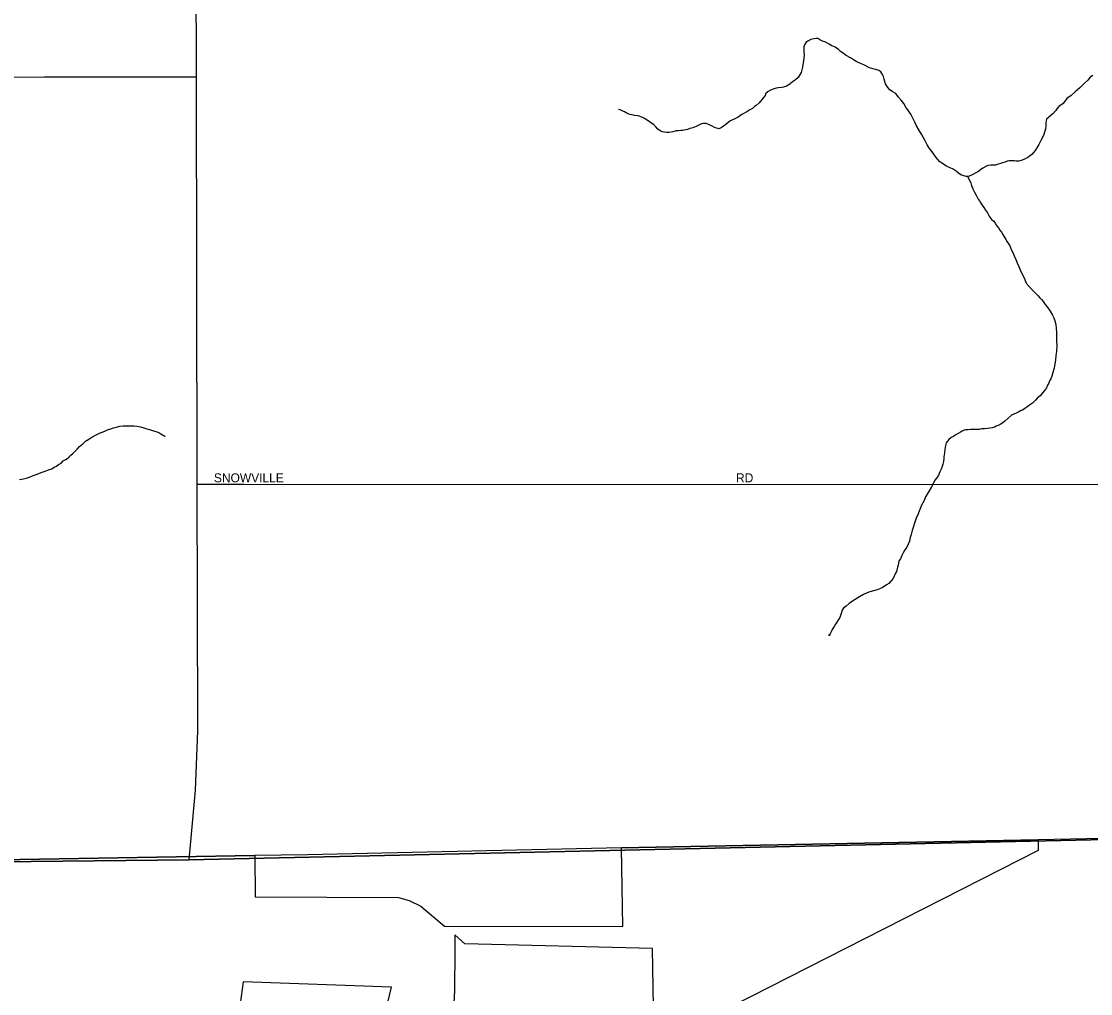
# Model space of a CAD drawing. Extents: x 2010165 to 2382125, y 1060529 to 1407316.
# Drawn here: x 2207531 to 2213496, y 1194340 to 1199766 of the extents above; entities that cross this region are included whole.
import ezdxf

# ---------------------------------------------------------------- set-up
doc = ezdxf.new("R2010")
doc.units = 0
for name, color, linetype in [('GM_X_Adjacent_County', 7, 'Continuous'), ('GM_X_City_Street', 7, 'Continuous'), ('GM_X_City_Street_Text', 7, 'Continuous'), ('GM_X_Corporation', 7, 'Continuous'), ('GM_X_County', 7, 'Continuous'), ('GM_X_Minor_River', 7, 'Continuous'), ('GM_X_State_Route', 7, 'Continuous')]:
    doc.layers.add(name, color=color, linetype=linetype)

msp = doc.modelspace()

# ---------------------------------------------------------------- linework, layer by layer
at = {"layer": 'GM_X_Adjacent_County'}
msp.add_lwpolyline([(2192737.6, 1194839.7), (2198605.6, 1194974.2), (2199009.7, 1194982.8), (2204631.8, 1195039.6), (2205347.9, 1195050.5), (2205386.6, 1195051.1), (2205910.4, 1195059.1), (2205996.9, 1195060.4), (2208466.7, 1195086.6), (2214754.4, 1195227), (2218436, 1195308), (2224284, 1195428.9)], dxfattribs=at)
at = {"layer": 'GM_X_City_Street'}
for points in [[(2204724.3, 1199441.2), (2204863.3, 1199441.5), (2205439.3, 1199448.7), (2205835.5, 1199453.6), (2206070.1, 1199453.8), (2207659.8, 1199455.3)], [(2207659.8, 1199455.3), (2208507.6, 1199456)], [(2208511.1, 1197183.4), (2208774.3, 1197183.4)], [(2208774.3, 1197183.4), (2214667.7, 1197181.8), (2216899.7, 1197183.8), (2217311.7, 1197172.5), (2217783.8, 1197165.3), (2218121.8, 1197163.9), (2218293.8, 1197148.2), (2218441.8, 1197144.5), (2218681.8, 1197136.8), (2218819.8, 1197131.1), (2219725.7, 1197182.9)]]:
    msp.add_lwpolyline(points, dxfattribs=at)
at = {"layer": 'GM_X_Corporation'}
for points in [[(2225489.9, 1195453.9), (2213202.5, 1195199), (2210879.2, 1195154.6), (2209126.8, 1195115.5), (2208833.2, 1195110.6), (2205335.3, 1195051.8), (2197309.3, 1194916.9), (2196632.3, 1194905.5), (2196205.1, 1208275.6), (2197215.9, 1208288.2), (2199497, 1208304.3), (2199654.4, 1208314.4), (2199834.9, 1208326), (2199872.3, 1208332.6), (2204445.3, 1208317.3), (2204662.3, 1210529.8), (2204447.2, 1221938.7)], [(2205380.8, 1189374), (2205335.3, 1195051.8), (2208833.2, 1195110.6), (2208834.3, 1194880.4), (2209634.8, 1194876.7), (2209694, 1194860.1), (2209758.7, 1194828.6), (2209892.1, 1194715.8), (2210886.7, 1194715.4), (2210879.2, 1195154.6), (2213202.5, 1195199), (2213203.5, 1195138.9), (2211060.9, 1194048.1), (2211051.6, 1194591.3), (2210004.4, 1194618.8), (2209949.2, 1194667.7), (2209948.6, 1194580.7), (2209946.9, 1194358.4), (2209934.6, 1194108.7)], [(2209535.9, 1194128.5), (2209596.2, 1194375.8), (2208768, 1194406.3), (2208752.2, 1194282.5)]]:
    msp.add_lwpolyline(points, dxfattribs=at)
at = {"layer": 'GM_X_County'}
msp.add_lwpolyline([(2224284, 1195428.9), (2218436, 1195308), (2214754.4, 1195227), (2208466.7, 1195086.6), (2205996.9, 1195060.4), (2205910.4, 1195059.1), (2205386.6, 1195051.1), (2205347.9, 1195050.5), (2204631.8, 1195039.6), (2199009.7, 1194982.8), (2198605.6, 1194974.2), (2192737.6, 1194839.7)], dxfattribs=at)
at = {"layer": 'GM_X_Minor_River'}
for points in [[(2212925, 1198961.5), (2212911, 1198955.3), (2212895.1, 1198947), (2212881.2, 1198936.8), (2212867.3, 1198926.6), (2212827.5, 1198906), (2212813.6, 1198899.8), (2212801.5, 1198899.7), (2212783.4, 1198905.4), (2212771.4, 1198909.3), (2212759.2, 1198919.2), (2212745.1, 1198929.1), (2212728.9, 1198940.9), (2212712.7, 1198948.7), (2212694.6, 1198956.5), (2212680.5, 1198964.4), (2212666.3, 1198974.2), (2212654.2, 1198982.1), (2212644, 1198994), (2212633.9, 1199005.9), (2212621.6, 1199023.9), (2212611.4, 1199037.8), (2212597.1, 1199055.7), (2212584.8, 1199077.6), (2212570.5, 1199103.5), (2212552, 1199135.4), (2212537.7, 1199161.3), (2212525.4, 1199183.3), (2212515.1, 1199203.2), (2212504.8, 1199225.2), (2212492.5, 1199247.1), (2212480.2, 1199267), (2212465.9, 1199286.9), (2212453.6, 1199306.9), (2212439.3, 1199326.8), (2212423.1, 1199344.6), (2212408.8, 1199362.5), (2212388.6, 1199374.3), (2212376.5, 1199384.2), (2212366.3, 1199394.1), (2212358.1, 1199408), (2212352, 1199418), (2212347.8, 1199430), (2212343.6, 1199444), (2212341.4, 1199458), (2212335.3, 1199470), (2212325.1, 1199483.9), (2212315, 1199491.8), (2212302.9, 1199495.7), (2212288.8, 1199499.5), (2212274.7, 1199503.4), (2212262.7, 1199507.2), (2212230.4, 1199522.9), (2212212.3, 1199530.7), (2212192.1, 1199540.5), (2212174, 1199550.3), (2212155.8, 1199562.1), (2212131.5, 1199575.8), (2212115.4, 1199587.7), (2212101.2, 1199597.5), (2212089, 1199609.4), (2212070.8, 1199621.2), (2212052.7, 1199629), (2212036.5, 1199638.9), (2212024.4, 1199646.8), (2212012.4, 1199650.6), (2212000.3, 1199654.5), (2211986.2, 1199662.3), (2211974, 1199670.2), (2211964, 1199670.1), (2211952, 1199667.9), (2211936, 1199663.7), (2211918.1, 1199655.4), (2211908.2, 1199649.3), (2211900.3, 1199635.1), (2211896.5, 1199623), (2211896.7, 1199609), (2211896.8, 1199596.9), (2211897.1, 1199574.8), (2211893.5, 1199546.7), (2211887.9, 1199510.5), (2211880.3, 1199480.3), (2211870.5, 1199462.1), (2211864.7, 1199451.9), (2211848.8, 1199439.7), (2211832.9, 1199427.4), (2211817.1, 1199415.2), (2211799.2, 1199404.9), (2211783.2, 1199398.7), (2211773.2, 1199396.6), (2211755.2, 1199394.3), (2211741.2, 1199392.1), (2211725.2, 1199387.9), (2211709.3, 1199381.7), (2211697.4, 1199373.5), (2211681.5, 1199361.3), (2211679.6, 1199351.2), (2211663.9, 1199330.9), (2211646.1, 1199310.6), (2211630.3, 1199296.3), (2211620.3, 1199290.2)], [(2213507.5, 1199462.9), (2213493.6, 1199454.7), (2213479.8, 1199438.4), (2213460, 1199418.1), (2213436.2, 1199395.7), (2213410.5, 1199373.3), (2213386.7, 1199352.9), (2213362.9, 1199334.5), (2213343.2, 1199308.2), (2213319.4, 1199289.8), (2213307.5, 1199277.6), (2213301.7, 1199267.5), (2213287.9, 1199251.2), (2213250.2, 1199220.6), (2213246.5, 1199198.5), (2213246.7, 1199180.4), (2213244.9, 1199166.3), (2213241.1, 1199152.2), (2213233.4, 1199128.1), (2213219.6, 1199103.8), (2213207.9, 1199079.5), (2213196.2, 1199059.3), (2213186.4, 1199045.1), (2213168.6, 1199022.8), (2213144.8, 1199006.4), (2213122.9, 1198994.1), (2213108.9, 1198989.9), (2213095, 1198985.7), (2213078.9, 1198985.5), (2213068.9, 1198987.4), (2213050.9, 1198987.2), (2213040.8, 1198987.1), (2213030.8, 1198984.9), (2213016.9, 1198980.7), (2213004.9, 1198976.6), (2212992.9, 1198972.4), (2212981, 1198968.2), (2212965, 1198964), (2212951, 1198963.8), (2212939, 1198963.7), (2212925, 1198961.5)], [(2211620.3, 1199290.2), (2211610.4, 1199280), (2211594.5, 1199271.8), (2211578.6, 1199261.6), (2211550.8, 1199245.1), (2211528.9, 1199230.8), (2211507, 1199220.5), (2211495.1, 1199214.3), (2211483.1, 1199208.1), (2211461.3, 1199189.8), (2211447.4, 1199181.6), (2211435.5, 1199171.4), (2211421.6, 1199165.2), (2211397.4, 1199172.9), (2211385.3, 1199180.8), (2211373.2, 1199186.6), (2211361.1, 1199192.5), (2211351.1, 1199196.4), (2211337, 1199196.2), (2211325, 1199194.1), (2211313.1, 1199187.9), (2211299.1, 1199181.7), (2211277.2, 1199171.4), (2211259.3, 1199167.1), (2211247.3, 1199162.9), (2211235.3, 1199160.8), (2211221.3, 1199156.6), (2211209.3, 1199156.4), (2211197.3, 1199154.3), (2211183.3, 1199154.1), (2211165.3, 1199149.9), (2211143.3, 1199145.6), (2211129.3, 1199145.4), (2211119.3, 1199147.3), (2211105.2, 1199149.1), (2211095.1, 1199155), (2211081, 1199164.8), (2211070.8, 1199176.8), (2211058.6, 1199188.7), (2211022.2, 1199214.3), (2211008.1, 1199224.2), (2210991.9, 1199232), (2210971.8, 1199237.8), (2210951.8, 1199239.5), (2210937.7, 1199243.3), (2210925.6, 1199245.2), (2210915.6, 1199249.1), (2210905.5, 1199255), (2210895.4, 1199260.9), (2210883.3, 1199266.7), (2210871.2, 1199272.6), (2210861.2, 1199274.5)], [(2212808.2, 1198899.7), (2212828.1, 1198863.8), (2212832.2, 1198849.8), (2212838.5, 1198831.9), (2212848.8, 1198811.9), (2212857, 1198795.9), (2212863.2, 1198784), (2212869.3, 1198774), (2212875.4, 1198764.1), (2212883.6, 1198752.1), (2212891.8, 1198740.2), (2212900, 1198726.2), (2212910.2, 1198712.3), (2212920.4, 1198696.4), (2212930.7, 1198678.4), (2212942.9, 1198660.5), (2212955.1, 1198650.6), (2212963.2, 1198638.7), (2212971.4, 1198626.7), (2212981.6, 1198612.8), (2212989.8, 1198600.9), (2212997.9, 1198588.9), (2213006.1, 1198577), (2213012.2, 1198567), (2213022.5, 1198549.1), (2213030.7, 1198535.1), (2213043, 1198517.2), (2213049.1, 1198503.2), (2213055.3, 1198489.2), (2213061.5, 1198475.3), (2213069.8, 1198457.3), (2213078.1, 1198437.3), (2213086.3, 1198417.4), (2213094.6, 1198397.4), (2213107, 1198369.4), (2213119.3, 1198345.5), (2213129.6, 1198325.5), (2213135.9, 1198305.6), (2213168.4, 1198269.8), (2213180.6, 1198255.9), (2213192.7, 1198246), (2213202.9, 1198234.1), (2213211.1, 1198224.2), (2213221.2, 1198214.3), (2213231.4, 1198202.3), (2213241.6, 1198186.4), (2213253.8, 1198172.5), (2213270.2, 1198148.6), (2213282.5, 1198126.7), (2213290.7, 1198110.7), (2213296.9, 1198094.8), (2213301.2, 1198074.7), (2213303.5, 1198052.7), (2213305.7, 1198030.6), (2213306, 1198012.5), (2213306.2, 1197998.5), (2213306.4, 1197980.4), (2213306.7, 1197956.3), (2213305.1, 1197924.2), (2213301.4, 1197902), (2213299.7, 1197875.9), (2213296, 1197853.8), (2213292.3, 1197829.6), (2213284.6, 1197805.4), (2213278.9, 1197785.3), (2213273.1, 1197771.2), (2213267.2, 1197759), (2213263.4, 1197746.9), (2213255.5, 1197734.8), (2213249.7, 1197720.7), (2213237.8, 1197706.5), (2213228, 1197692.3), (2213214.2, 1197676), (2213200.3, 1197665.8), (2213188.5, 1197651.6), (2213172.6, 1197635.3), (2213154.8, 1197623.1), (2213140.9, 1197612.8), (2213129, 1197604.7), (2213115, 1197596.4), (2213105.1, 1197592.3), (2213095.1, 1197586.2), (2213085.2, 1197582), (2213067.3, 1197573.8), (2213055.3, 1197567.6), (2213033.5, 1197549.2), (2213017.7, 1197535), (2213005.8, 1197524.8), (2212991.9, 1197516.6), (2212979.9, 1197510.4), (2212969.9, 1197506.2), (2212960, 1197502.1), (2212946, 1197497.9), (2212934, 1197495.8), (2212920, 1197493.6), (2212904, 1197491.4), (2212888, 1197491.1), (2212874, 1197489), (2212860, 1197488.8), (2212839.9, 1197488.5), (2212825.9, 1197488.3)], [(2207818.8, 1197354.5), (2207830.5, 1197366.9), (2207842.2, 1197379.2), (2207855.9, 1197393.6), (2207873.5, 1197408.2), (2207889.2, 1197422.6), (2207906.9, 1197435.1), (2207924.7, 1197445.6), (2207948.4, 1197458.3), (2207966.2, 1197466.8), (2207982.1, 1197473.2), (2207995.9, 1197479.6), (2208011.8, 1197486.1), (2208029.7, 1197492.6), (2208045.6, 1197497), (2208061.5, 1197501.4), (2208079.4, 1197505.9), (2208099.4, 1197508.5), (2208117.5, 1197508.9), (2208135.5, 1197509.4), (2208159.6, 1197508), (2208177.7, 1197506.5), (2208195.8, 1197503), (2208214, 1197497.4), (2208230.2, 1197491.8), (2208246.4, 1197488.2), (2208262.6, 1197482.6), (2208280.7, 1197477.1), (2208296.9, 1197471.5), (2208309.2, 1197463.8), (2208331.6, 1197450.3), (2208331.7, 1197448.3)], [(2212825.9, 1197488.3), (2212811.9, 1197486.2), (2212799.9, 1197486), (2212789.9, 1197483.9), (2212779.9, 1197479.7), (2212770, 1197473.6), (2212756.1, 1197465.4), (2212740.2, 1197457.1), (2212730.3, 1197449), (2212718.3, 1197442.8), (2212704.4, 1197432.6), (2212690.6, 1197414.3), (2212686.8, 1197398.2), (2212683.1, 1197376.1), (2212681.4, 1197358), (2212679.5, 1197345.9), (2212677.6, 1197335.9), (2212677.8, 1197323.8), (2212676, 1197309.7), (2212672.1, 1197295.6), (2212668.3, 1197281.5), (2212662.5, 1197267.4), (2212654.7, 1197251.2), (2212646.9, 1197233.1), (2212637.1, 1197218.9), (2212627.2, 1197204.7), (2212619.4, 1197188.5), (2212607.7, 1197168.3), (2212595.9, 1197146.1), (2212584.2, 1197127.8), (2212574.4, 1197111.7), (2212566.6, 1197091.5), (2212552.9, 1197065.2), (2212529.6, 1197008.7), (2212523.7, 1196998.6), (2212519.9, 1196982.4), (2212514.1, 1196966.3), (2212508.4, 1196946.1), (2212500.7, 1196924), (2212494.9, 1196901.8), (2212489.1, 1196885.7), (2212485.4, 1196865.5), (2212477.6, 1196847.4), (2212469.8, 1196831.2), (2212460, 1196817), (2212450.2, 1196800.8), (2212442.4, 1196784.7), (2212434.6, 1196766.5), (2212428.7, 1196756.4), (2212424.9, 1196744.3), (2212423, 1196730.2), (2212419.2, 1196720.1), (2212413.5, 1196695.9), (2212407.6, 1196685.8), (2212393.9, 1196657.5), (2212370.3, 1196629.1), (2212356.3, 1196620.9), (2212332.5, 1196604.6), (2212304.6, 1196594.2), (2212284.6, 1196587.9), (2212264.7, 1196581.6), (2212248.7, 1196577.4), (2212228.8, 1196567.1), (2212206.9, 1196554.8), (2212173.1, 1196534.2), (2212149.3, 1196517.9), (2212131.5, 1196501.6), (2212117.6, 1196491.4), (2212109.7, 1196479.2), (2212104, 1196461.1), (2212096.2, 1196438.9), (2212072.7, 1196402.4), (2212064.8, 1196388.3), (2212055, 1196372.1), (2212049.2, 1196360), (2212041.4, 1196343.8), (2212033.4, 1196339.7), (2212043.4, 1196339.8)], [(2207519.9, 1197210.1), (2207541.9, 1197212.7), (2207559.8, 1197217.2), (2207579.7, 1197223.8), (2207597.5, 1197232.2), (2207619.4, 1197238.8), (2207641.2, 1197247.5), (2207663.1, 1197256.1), (2207682.9, 1197262.6), (2207700.8, 1197269.1), (2207714.6, 1197277.5), (2207726.5, 1197283.8), (2207738.3, 1197292.2), (2207752.1, 1197300.6), (2207763.8, 1197312.9), (2207783.6, 1197323.5), (2207795.3, 1197333.8), (2207807.1, 1197344.2), (2207818.8, 1197354.5)]]:
    msp.add_lwpolyline(points, dxfattribs=at)
at = {"layer": 'GM_X_State_Route'}
for points in [[(2208507.5, 1199487.9), (2208498.3, 1202183.8), (2208496.5, 1203898.9), (2208487.9, 1206109.2), (2208480.8, 1208362.2), (2208479.2, 1208771.6)], [(2208514.8, 1195827.4), (2208511.1, 1197183.4), (2208507.6, 1199456), (2208507.5, 1199487.9)], [(2208466.7, 1195086.6), (2208501.6, 1195475.3), (2208514.8, 1195807.3), (2208514.8, 1195827.4)]]:
    msp.add_lwpolyline(points, dxfattribs=at)

# ---------------------------------------------------------------- texts
at = {"layer": 'GM_X_City_Street_Text'}
for s, p in [('SNOWVILLE', (2208605, 1197193.4)), ('RD', (2211517.8, 1197193.4))]:
    msp.add_text(s, height=50, rotation=0.00001, dxfattribs=at).set_placement(p)

doc.saveas('drawing.dxf')
